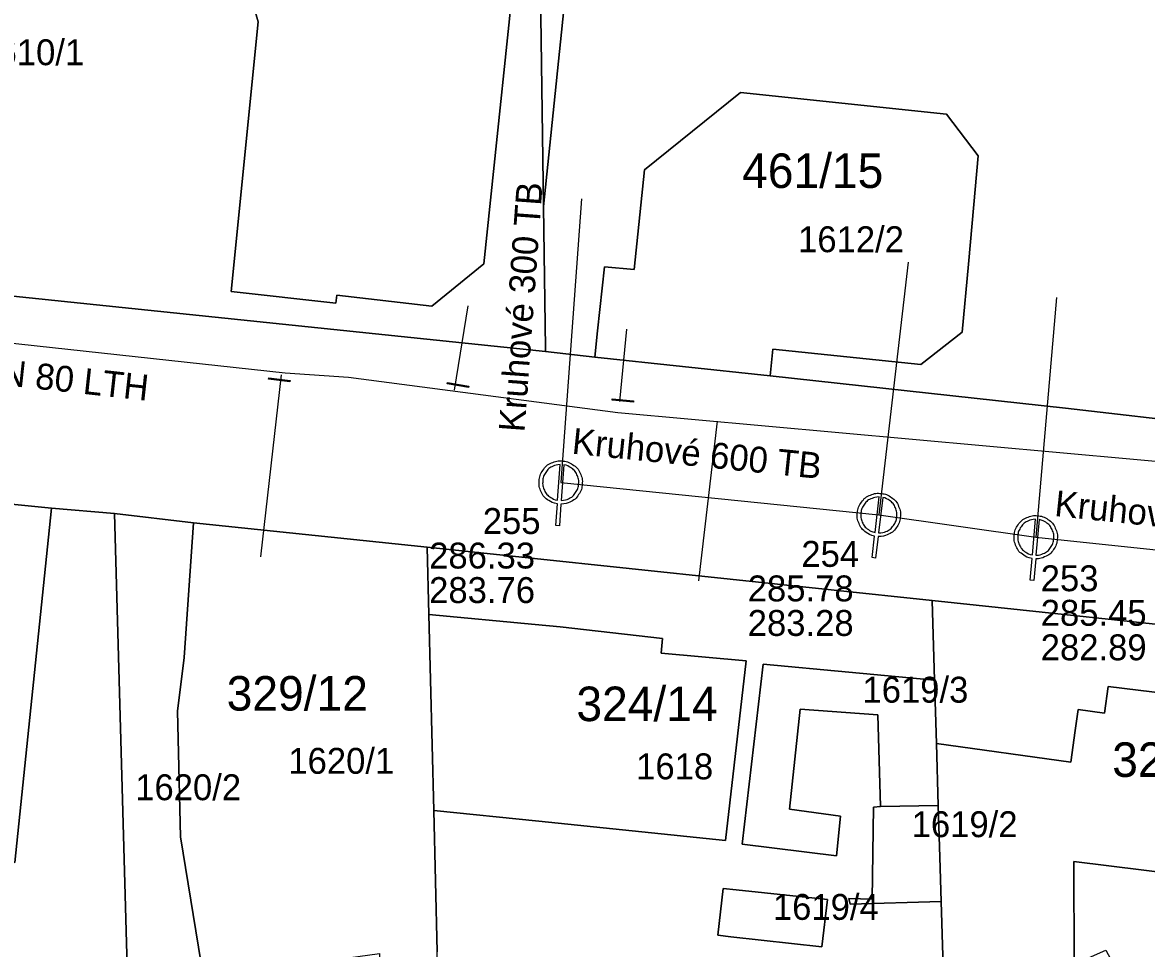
# Model space of a CAD drawing. Extents: x -570698 to -570232, y -1086952 to -1086596.
# Drawn here: x -570540.7 to -570475.5, y -1086776.7 to -1086723.1 of the extents above; entities that cross this region are included whole.
import ezdxf

# ---------------------------------------------------------------- set-up
doc = ezdxf.new("R2010")
doc.units = 0
for name, color, linetype in [('Adresní místo-text', 7, 'Continuous'), ('Armatura vodovodní', 7, 'Continuous'), ('Default', 7, 'Continuous'), ('Kanalizační přípojka', 7, 'Continuous'), ('Kanalizační stoka', 7, 'Continuous'), ('Kanalizační šachta', 7, 'Continuous'), ('Parcela-polygon', 7, 'Continuous'), ('Parcela-text', 7, 'Continuous'), ('Popis kmenové stoky', 7, 'Continuous'), ('Popis šachty', 7, 'Continuous'), ('Vodovodní přípojka', 7, 'Continuous'), ('Vodovodní řad', 7, 'Continuous'), ('Řad vodovodní popis', 7, 'Continuous')]:
    doc.layers.add(name, color=color, linetype=linetype)

msp = doc.modelspace()

# ---------------------------------------------------------------- linework, layer by layer
at = {"layer": 'Armatura vodovodní'}
for points in [[(-570526.397, -1086743.674), (-570525.155, -1086743.814), (-570525.163, -1086743.892), (-570526.406, -1086743.751), (-570526.397, -1086743.674)], [(-570516.044, -1086743.942), (-570514.811, -1086744.143), (-570514.823, -1086744.22), (-570516.057, -1086744.019), (-570516.044, -1086743.942)], [(-570506.501, -1086744.877), (-570505.257, -1086745), (-570505.265, -1086745.078), (-570506.509, -1086744.954), (-570506.501, -1086744.877)]]:
    msp.add_lwpolyline(points, dxfattribs=at)
at = {"layer": 'Default'}
for points in [[(-570509.674, -1086750.967), (-570509.93, -1086750.931), (-570510.18, -1086750.766), (-570510.465, -1086750.581), (-570510.608, -1086750.272), (-570510.751, -1086749.963), (-570510.727, -1086749.639), (-570510.703, -1086749.313), (-570510.513, -1086749.025), (-570510.323, -1086748.738), (-570510.014, -1086748.599), (-570509.706, -1086748.46), (-570509.389, -1086748.483), (-570509.075, -1086748.506), (-570508.789, -1086748.689), (-570508.502, -1086748.871), (-570508.356, -1086749.183), (-570508.21, -1086749.495), (-570508.234, -1086749.821), (-570508.257, -1086750.145), (-570508.443, -1086750.43), (-570508.629, -1086750.715), (-570508.938, -1086750.857), (-570509.21, -1086750.984), (-570509.469, -1086750.982)], [(-570509.507, -1086748.688), (-570509.705, -1086748.69), (-570509.928, -1086748.789), (-570510.186, -1086748.905), (-570510.343, -1086749.144), (-570510.5, -1086749.384), (-570510.52, -1086749.654), (-570510.54, -1086749.924), (-570510.421, -1086750.18), (-570510.303, -1086750.436), (-570510.065, -1086750.591), (-570509.862, -1086750.725), (-570509.658, -1086750.755)], [(-570509.454, -1086750.77), (-570509.248, -1086750.77), (-570509.025, -1086750.667), (-570508.769, -1086750.548), (-570508.615, -1086750.312), (-570508.46, -1086750.076), (-570508.441, -1086749.806), (-570508.421, -1086749.536), (-570508.543, -1086749.276), (-570508.664, -1086749.016), (-570508.903, -1086748.864), (-570509.106, -1086748.734), (-570509.302, -1086748.703)], [(-570491.295, -1086752.837), (-570491.551, -1086752.791), (-570491.793, -1086752.615), (-570492.07, -1086752.418), (-570492.2, -1086752.104), (-570492.329, -1086751.789), (-570492.292, -1086751.466), (-570492.254, -1086751.141), (-570492.052, -1086750.862), (-570491.851, -1086750.583), (-570491.536, -1086750.458), (-570491.222, -1086750.332), (-570490.907, -1086750.368), (-570490.594, -1086750.404), (-570490.315, -1086750.599), (-570490.037, -1086750.793), (-570489.904, -1086751.111), (-570489.771, -1086751.429), (-570489.809, -1086751.754), (-570489.846, -1086752.076), (-570490.044, -1086752.353), (-570490.242, -1086752.63), (-570490.556, -1086752.758), (-570490.833, -1086752.874), (-570491.092, -1086752.861)], [(-570491.033, -1086750.567), (-570491.231, -1086750.562), (-570491.458, -1086750.651), (-570491.721, -1086750.756), (-570491.888, -1086750.988), (-570492.055, -1086751.221), (-570492.086, -1086751.49), (-570492.117, -1086751.759), (-570492.009, -1086752.02), (-570491.902, -1086752.281), (-570491.67, -1086752.445), (-570491.473, -1086752.588), (-570491.271, -1086752.626)], [(-570491.067, -1086752.65), (-570490.862, -1086752.659), (-570490.635, -1086752.565), (-570490.374, -1086752.457), (-570490.21, -1086752.228), (-570490.046, -1086751.999), (-570490.015, -1086751.73), (-570489.984, -1086751.461), (-570490.094, -1086751.196), (-570490.205, -1086750.931), (-570490.437, -1086750.769), (-570490.635, -1086750.631), (-570490.829, -1086750.591)], [(-570482.17, -1086754.134), (-570482.427, -1086754.095), (-570482.674, -1086753.926), (-570482.957, -1086753.738), (-570483.095, -1086753.427), (-570483.234, -1086753.116), (-570483.206, -1086752.792), (-570483.178, -1086752.466), (-570482.984, -1086752.182), (-570482.79, -1086751.897), (-570482.479, -1086751.762), (-570482.169, -1086751.628), (-570481.852, -1086751.655), (-570481.539, -1086751.682), (-570481.255, -1086751.868), (-570480.971, -1086752.055), (-570480.829, -1086752.369), (-570480.687, -1086752.682), (-570480.715, -1086753.008), (-570480.743, -1086753.332), (-570480.933, -1086753.614), (-570481.123, -1086753.897), (-570481.434, -1086754.034), (-570481.707, -1086754.157), (-570481.966, -1086754.152)], [(-570481.973, -1086751.858), (-570482.171, -1086751.858), (-570482.395, -1086751.953), (-570482.655, -1086752.066), (-570482.815, -1086752.303), (-570482.976, -1086752.54), (-570482.999, -1086752.81), (-570483.022, -1086753.08), (-570482.908, -1086753.338), (-570482.793, -1086753.595), (-570482.556, -1086753.753), (-570482.355, -1086753.89), (-570482.152, -1086753.923)], [(-570481.948, -1086753.94), (-570481.742, -1086753.944), (-570481.518, -1086753.843), (-570481.26, -1086753.728), (-570481.103, -1086753.494), (-570480.945, -1086753.26), (-570480.922, -1086752.99), (-570480.898, -1086752.72), (-570481.017, -1086752.459), (-570481.135, -1086752.197), (-570481.371, -1086752.042), (-570481.573, -1086751.909), (-570481.769, -1086751.875)]]:
    msp.add_open_spline(points, degree=3, dxfattribs=at)
at = {"layer": 'Kanalizační přípojka'}
for p, q in [((-570489.355, -1086736.96), (-570491.05, -1086751.61)), ((-570480.757, -1086739.023), (-570481.96, -1086752.9))]:
    msp.add_line(p, q, dxfattribs=at)
at = {"layer": 'Kanalizační stoka'}
for p, q in [((-570508.278, -1086733.294), (-570509.48, -1086749.73)), ((-570509.48, -1086749.73), (-570491.05, -1086751.61)), ((-570491.05, -1086751.61), (-570481.96, -1086752.9)), ((-570481.96, -1086752.9), (-570445.14, -1086756.72))]:
    msp.add_line(p, q, dxfattribs=at)
at = {"layer": 'Kanalizační šachta'}
for points in [[(-570509.658, -1086750.755), (-570509.507, -1086748.688)], [(-570509.302, -1086748.703), (-570509.454, -1086750.77)], [(-570509.469, -1086750.982), (-570509.56, -1086752.231), (-570509.765, -1086752.216), (-570509.674, -1086750.967)], [(-570491.271, -1086752.626), (-570491.033, -1086750.567)], [(-570490.829, -1086750.591), (-570491.067, -1086752.65)], [(-570482.152, -1086753.923), (-570481.973, -1086751.858)], [(-570481.769, -1086751.875), (-570481.948, -1086753.94)], [(-570491.092, -1086752.861), (-570491.236, -1086754.105), (-570491.439, -1086754.082), (-570491.295, -1086752.837)], [(-570481.966, -1086754.152), (-570482.074, -1086755.4), (-570482.278, -1086755.382), (-570482.17, -1086754.134)]]:
    msp.add_lwpolyline(points, dxfattribs=at)
at = {"layer": 'Parcela-polygon'}
for points in [[(-570522.15, -1086694.08), (-570522.76, -1086692.12), (-570525.43, -1086688.51), (-570557.96, -1086703.7), (-570560.32, -1086736.37), (-570560.36, -1086736.95), (-570510.36, -1086742.15), (-570510.36, -1086741.94), (-570510.48, -1086733.74), (-570510.81, -1086710.35), (-570513.51, -1086707.69), (-570519.18, -1086700.57), (-570520.57, -1086699.73), (-570523.79, -1086695.31)], [(-570511.79, -1086716.57), (-570525.18, -1086700.08), (-570526.88, -1086699.81), (-570532.24, -1086704.16), (-570533.03, -1086703.22), (-570538, -1086707.21), (-570527.99, -1086719.57), (-570527, -1086723.04), (-570528.57, -1086738.67), (-570522.5, -1086739.34), (-570522.45, -1086738.88), (-570516.94, -1086739.51), (-570513.94, -1086737.07)], [(-570511.79, -1086716.57), (-570513.94, -1086737.07), (-570516.94, -1086739.51), (-570522.45, -1086738.88), (-570522.5, -1086739.34), (-570528.57, -1086738.67), (-570527, -1086723.04), (-570527.99, -1086719.57), (-570538, -1086707.21), (-570533.03, -1086703.22), (-570532.24, -1086704.16), (-570526.88, -1086699.81), (-570525.18, -1086700.08)], [(-570510.81, -1086710.35), (-570510.48, -1086733.74), (-570507.76, -1086707.35), (-570510.42, -1086707.24), (-570512.06, -1086708)], [(-570507.34, -1086740.94), (-570507.5, -1086742.46), (-570497.35, -1086743.56), (-570497.19, -1086742), (-570488.61, -1086742.89), (-570486.22, -1086741.03), (-570485.86, -1086737.09), (-570485.64, -1086734.7), (-570485.29, -1086730.81), (-570487.13, -1086728.4), (-570499.07, -1086727.14), (-570504.63, -1086731.62), (-570505.22, -1086737.4), (-570506.94, -1086737.23)], [(-570575.16, -1086747.45), (-570575.63, -1086752.18), (-570576.71, -1086763.1), (-570576.24, -1086767.98), (-570541.1, -1086771.74), (-570538.98, -1086751.22), (-570565.31, -1086748.59), (-570566.93, -1086748.39)], [(-570538.98, -1086751.22), (-570541.1, -1086771.74), (-570576.24, -1086767.98), (-570574.78, -1086782.97), (-570568.21, -1086782.35), (-570534.55, -1086779.16), (-570535.32, -1086751.53)], [(-570535.32, -1086751.53), (-570534.55, -1086779.16), (-570534.47, -1086781.74), (-570529.59, -1086781.76), (-570530.17, -1086778.41), (-570531.51, -1086770.26), (-570531.68, -1086762.98), (-570531.29, -1086759.87), (-570530.75, -1086752.07)], [(-570530.75, -1086752.07), (-570531.29, -1086759.87), (-570531.68, -1086762.98), (-570531.51, -1086770.26), (-570530.17, -1086778.41), (-570519.97, -1086777), (-570519.85, -1086785.1), (-570516.78, -1086785.02), (-570516.45, -1086785.02), (-570516.64, -1086776.92), (-570516.84, -1086768.72), (-570517.12, -1086757.38), (-570517.21, -1086753.48)], [(-570487.97, -1086756.56), (-570487.83, -1086761.17), (-570487.72, -1086764.85), (-570479.93, -1086765.93), (-570479.67, -1086764.1), (-570479.5, -1086762.88), (-570477.97, -1086763.08), (-570477.77, -1086761.55), (-570467.33, -1086762.82), (-570468.61, -1086773.22), (-570473.69, -1086772.58), (-570473.67, -1086772.43), (-570479.75, -1086771.68), (-570479.73, -1086777.62), (-570477.91, -1086776.82), (-570475.02, -1086782.19), (-570473.93, -1086782.13), (-570454.98, -1086781.11), (-570451.54, -1086760.42)], [(-570517.12, -1086757.38), (-570516.84, -1086768.72), (-570510.75, -1086769.34), (-570499.93, -1086770.46), (-570498.74, -1086760.06), (-570503.67, -1086759.61), (-570503.59, -1086758.77), (-570509.51, -1086758.08), (-570510.96, -1086757.95)], [(-570487.83, -1086761.17), (-570497.76, -1086760.25), (-570498.96, -1086770.68), (-570493.51, -1086771.35), (-570493.28, -1086769.05), (-570496.22, -1086768.65), (-570495.6, -1086762.86), (-570491.11, -1086763.19), (-570490.95, -1086768.49), (-570487.61, -1086768.44), (-570487.72, -1086764.85)], [(-570479.93, -1086765.93), (-570487.72, -1086764.85), (-570487.61, -1086768.44), (-570487.52, -1086771.42), (-570487.44, -1086773.99), (-570487.29, -1086779.03), (-570487.24, -1086780.88), (-570482.77, -1086778.94), (-570479.73, -1086777.62), (-570479.75, -1086771.68), (-570473.67, -1086772.43), (-570473.69, -1086772.58), (-570468.61, -1086773.22), (-570467.33, -1086762.82), (-570477.77, -1086761.55), (-570477.97, -1086763.08), (-570479.5, -1086762.88), (-570479.67, -1086764.1)], [(-570487.61, -1086768.44), (-570490.95, -1086768.49), (-570491.37, -1086768.54), (-570491.43, -1086773.86), (-570492.79, -1086773.83), (-570492.72, -1086774.15), (-570487.44, -1086773.99), (-570487.52, -1086771.42)], [(-570494.03, -1086773.89), (-570499.32, -1086773.33), (-570500.06, -1086773.25), (-570500.38, -1086775.95), (-570499.63, -1086776.04), (-570494.35, -1086776.62)], [(-570494.35, -1086776.62), (-570499.63, -1086776.04), (-570500.38, -1086775.95), (-570500.06, -1086773.25), (-570499.32, -1086773.33), (-570494.03, -1086773.89)]]:
    msp.add_lwpolyline(points, close=True, dxfattribs=at)
for points in [[(-570507.76, -1086707.35), (-570510.48, -1086733.74), (-570510.36, -1086741.94), (-570510.36, -1086742.15), (-570507.5, -1086742.46), (-570507.34, -1086740.94), (-570506.94, -1086737.23), (-570505.22, -1086737.4), (-570504.63, -1086731.62), (-570499.07, -1086727.14), (-570487.13, -1086728.4), (-570485.29, -1086730.81), (-570485.64, -1086734.7), (-570485.86, -1086737.09), (-570486.22, -1086741.03), (-570488.61, -1086742.89), (-570497.19, -1086742), (-570497.35, -1086743.56), (-570480.24, -1086745.42), (-570471.87, -1086746.39)], [(-570565.31, -1086748.59), (-570538.98, -1086751.22), (-570535.32, -1086751.53), (-570530.75, -1086752.07), (-570517.21, -1086753.48), (-570487.97, -1086756.56), (-570451.54, -1086760.42), (-570447.91, -1086760.81), (-570445.98, -1086761.06), (-570457.51, -1086746.72), (-570469.87, -1086745.3), (-570470.47, -1086746.1), (-570471.87, -1086746.39), (-570480.24, -1086745.42), (-570497.35, -1086743.56), (-570507.5, -1086742.46), (-570510.36, -1086742.15), (-570560.36, -1086736.95)], [(-570487.29, -1086779.03), (-570487.44, -1086773.99), (-570492.72, -1086774.15), (-570492.79, -1086773.83), (-570491.43, -1086773.86), (-570491.37, -1086768.54), (-570490.95, -1086768.49), (-570491.11, -1086763.19), (-570495.6, -1086762.86), (-570496.22, -1086768.65), (-570493.28, -1086769.05), (-570493.51, -1086771.35), (-570498.96, -1086770.68), (-570497.76, -1086760.25), (-570487.83, -1086761.17), (-570487.97, -1086756.56), (-570517.21, -1086753.48), (-570517.12, -1086757.38), (-570510.96, -1086757.95), (-570509.51, -1086758.08), (-570503.59, -1086758.77), (-570503.67, -1086759.61), (-570498.74, -1086760.06), (-570499.93, -1086770.46), (-570510.75, -1086769.34), (-570516.84, -1086768.72), (-570516.64, -1086776.92)]]:
    msp.add_lwpolyline(points, dxfattribs=at)
at = {"layer": 'Vodovodní přípojka'}
msp.add_line((-570506.057, -1086745.033), (-570505.642, -1086740.854), dxfattribs=at)
for points in [[(-570515.633, -1086744.38), (-570514.837, -1086739.501)], [(-570525.681, -1086743.484), (-570526.875, -1086754.037)], [(-570500.411, -1086746.172), (-570501.505, -1086755.43)]]:
    msp.add_lwpolyline(points, dxfattribs=at)
at = {"layer": 'Vodovodní řad'}
msp.add_lwpolyline([(-570635.869, -1086748.204), (-570627.454, -1086745.196), (-570625.992, -1086744.673), (-570622.641, -1086743.475), (-570608.586, -1086738.452), (-570602.698, -1086736.347), (-570599.653, -1086735.74), (-570598.114, -1086735.687), (-570585.97, -1086736.946), (-570560.213, -1086739.597), (-570525.451, -1086743.384), (-570521.774, -1086743.637), (-570506.17, -1086745.665), (-570467.773, -1086749.146), (-570443.576, -1086752.528)], dxfattribs=at)

# ---------------------------------------------------------------- texts
at = {"layer": 'Adresní místo-text'}
for s, p in [('461/15', (-570498.971, -1086732.67)), ('329/12', (-570528.831, -1086762.94)), ('324/14', (-570508.571, -1086763.55)), ('320/16', (-570477.531, -1086766.78))]:
    msp.add_text(s, height=2, dxfattribs=at).set_placement(p)
at = {"layer": 'Parcela-text'}
for s, p in [('1610/1', (-570543.22, -1086725.56)), ('1612/2', (-570495.73, -1086736.39)), ('1619/3', (-570492, -1086762.48)), ('1620/1', (-570525.26, -1086766.6)), ('1618', (-570505.11, -1086766.92)), ('1620/2', (-570534.13, -1086768.13)), ('1619/2', (-570489.15, -1086770.27)), ('1619/4', (-570497.19, -1086775.06))]:
    msp.add_text(s, height=1.5, dxfattribs=at).set_placement(p)
at = {"layer": 'Popis kmenové stoky'}
for s, rotation, p in [('Kruhové 300 TB', 85.81727, (-570511.58, -1086746.842)), ('Kruhové 600 TB', 354.17558, (-570508.873, -1086748.054)), ('Kruhové 600 TB', 354.07686, (-570480.917, -1086751.666))]:
    msp.add_text(s, height=1.5, rotation=rotation, dxfattribs=at).set_placement(p)
at = {"layer": 'Popis šachty'}
for s, p in [('255', (-570513.995, -1086752.71)), ('254', (-570495.54, -1086754.614)), ('286.33', (-570517.102, -1086754.71)), ('285.78', (-570498.647, -1086756.614)), ('253', (-570481.674, -1086756.026)), ('283.76', (-570517.102, -1086756.71)), ('285.45', (-570481.674, -1086758.026)), ('283.28', (-570498.647, -1086758.614)), ('282.89', (-570481.674, -1086760.026))]:
    msp.add_text(s, height=1.5, dxfattribs=at).set_placement(p)
at = {"layer": 'Řad vodovodní popis'}
msp.add_text('DN 80 LTH', height=1.5, rotation=353.7827, dxfattribs=at).set_placement((-570543.407, -1086743.913))

doc.saveas('drawing.dxf')
